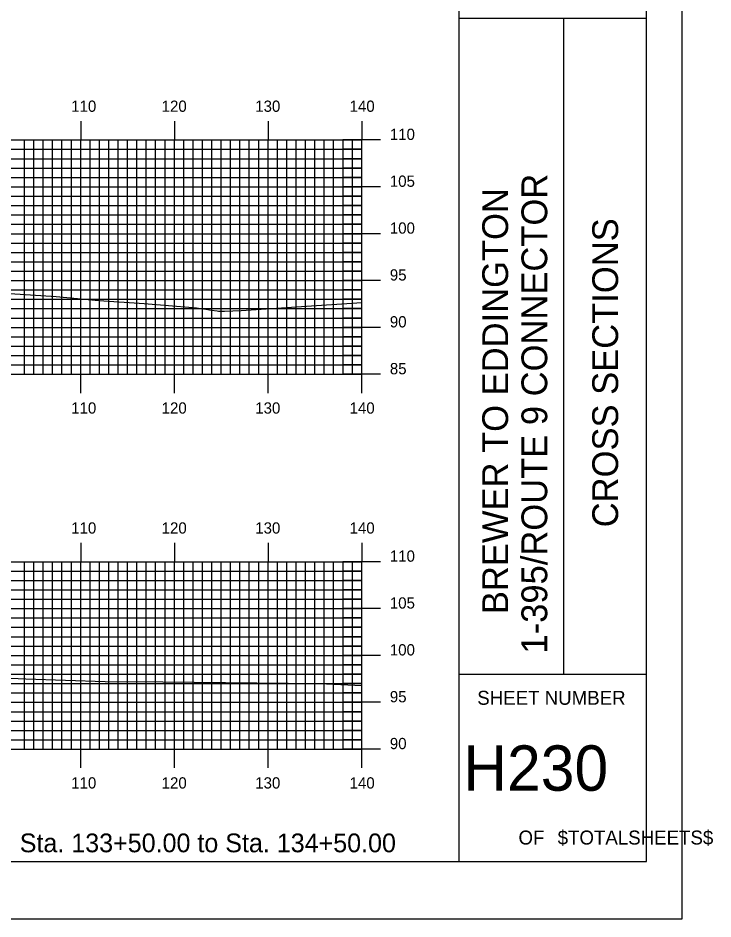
# Model space of a CAD drawing. Extents: x 1774777 to 1775120, y 442591 to 442811.
# Drawn here: x 1775046 to 1775120.2, y 442590.5 to 442686.7 of the extents above; entities that cross this region are included whole.
import ezdxf

# ---------------------------------------------------------------- set-up
doc = ezdxf.new("R2010")
doc.units = 0
for name, color, linetype in [('BORDER', 7, 'Continuous'), ('H_V ANNOTATION', 7, 'Continuous'), ('MAJOR', 7, 'Continuous'), ('MINOR', 7, 'Continuous'), ('PLOT BOUNDARY', 7, 'Continuous'), ('S_Roadway_Centerline', 7, 'Continuous')]:
    doc.layers.add(name, color=color, linetype=linetype)

msp = doc.modelspace()

# ---------------------------------------------------------------- linework, layer by layer
at = {"layer": 'BORDER'}
for p, q in [((1775093.085, 442596.665), (1775093.085, 442806.665)), ((1775093.085, 442686.671), (1775113.085, 442686.671)), ((1775104.267, 442616.671), (1775104.267, 442686.671)), ((1775093.085, 442616.671), (1775113.085, 442616.671))]:
    msp.add_line(p, q, dxfattribs=at)
msp.add_lwpolyline([(1774793.085, 442596.665), (1775113.085, 442596.665), (1775113.085, 442806.665), (1774793.085, 442806.665)], close=True, dxfattribs=at)
at = {"layer": 'MAJOR'}
for p, q in [((1775052.685, 442675.669), (1775052.685, 442673.665)), ((1775062.685, 442675.669), (1775062.685, 442673.665)), ((1775072.685, 442675.669), (1775072.685, 442673.665)), ((1775082.685, 442675.669), (1775082.685, 442673.665)), ((1774802.685, 442673.665), (1775082.685, 442673.665)), ((1774802.685, 442673.665), (1775082.685, 442673.665)), ((1775052.685, 442648.665), (1775052.685, 442673.665)), ((1775062.685, 442648.665), (1775062.685, 442673.665)), ((1775072.685, 442648.665), (1775072.685, 442673.665)), ((1775084.689, 442673.665), (1775080.681, 442673.665)), ((1775082.685, 442648.665), (1775082.685, 442673.665)), ((1775082.685, 442648.665), (1775082.685, 442673.665)), ((1774802.685, 442668.665), (1775082.685, 442668.665)), ((1775084.689, 442668.665), (1775080.681, 442668.665)), ((1774802.685, 442663.665), (1775082.685, 442663.665)), ((1775084.689, 442663.665), (1775080.681, 442663.665)), ((1774802.685, 442658.665), (1775082.685, 442658.665)), ((1775084.689, 442658.665), (1775080.681, 442658.665)), ((1774802.685, 442653.665), (1775082.685, 442653.665)), ((1775084.689, 442653.665), (1775080.681, 442653.665)), ((1774802.685, 442648.665), (1775082.685, 442648.665)), ((1774802.685, 442648.665), (1775082.685, 442648.665)), ((1775052.685, 442646.661), (1775052.685, 442648.665)), ((1775062.685, 442646.661), (1775062.685, 442648.665)), ((1775072.685, 442646.661), (1775072.685, 442648.665)), ((1775084.689, 442648.665), (1775080.681, 442648.665)), ((1775082.685, 442646.661), (1775082.685, 442648.665)), ((1775052.685, 442630.669), (1775052.685, 442628.665)), ((1775062.685, 442630.669), (1775062.685, 442628.665)), ((1775072.685, 442630.669), (1775072.685, 442628.665)), ((1775082.685, 442630.669), (1775082.685, 442628.665)), ((1774802.685, 442628.665), (1775082.685, 442628.665)), ((1774802.685, 442628.665), (1775082.685, 442628.665)), ((1775052.685, 442608.665), (1775052.685, 442628.665)), ((1775062.685, 442608.665), (1775062.685, 442628.665)), ((1775072.685, 442608.665), (1775072.685, 442628.665)), ((1775084.689, 442628.665), (1775080.681, 442628.665)), ((1775082.685, 442608.665), (1775082.685, 442628.665)), ((1775082.685, 442608.665), (1775082.685, 442628.665)), ((1774802.685, 442623.665), (1775082.685, 442623.665)), ((1775084.689, 442623.665), (1775080.681, 442623.665)), ((1774802.685, 442618.665), (1775082.685, 442618.665)), ((1775084.689, 442618.665), (1775080.681, 442618.665)), ((1774802.685, 442613.665), (1775082.685, 442613.665)), ((1775084.689, 442613.665), (1775080.681, 442613.665)), ((1774802.685, 442608.665), (1775082.685, 442608.665)), ((1774802.685, 442608.665), (1775082.685, 442608.665)), ((1775052.685, 442606.661), (1775052.685, 442608.665)), ((1775062.685, 442606.661), (1775062.685, 442608.665)), ((1775072.685, 442606.661), (1775072.685, 442608.665)), ((1775084.689, 442608.665), (1775080.681, 442608.665)), ((1775082.685, 442606.661), (1775082.685, 442608.665))]:
    msp.add_line(p, q, dxfattribs=at)
at = {"layer": 'MINOR'}
for p, q in [((1775046.685, 442648.665), (1775046.685, 442673.665)), ((1775047.685, 442648.665), (1775047.685, 442673.665)), ((1775048.685, 442648.665), (1775048.685, 442673.665)), ((1775049.685, 442648.665), (1775049.685, 442673.665)), ((1775050.685, 442648.665), (1775050.685, 442673.665)), ((1775051.685, 442648.665), (1775051.685, 442673.665)), ((1775053.685, 442648.665), (1775053.685, 442673.665)), ((1775054.685, 442648.665), (1775054.685, 442673.665)), ((1775055.685, 442648.665), (1775055.685, 442673.665)), ((1775056.685, 442648.665), (1775056.685, 442673.665)), ((1775057.685, 442648.665), (1775057.685, 442673.665)), ((1775058.685, 442648.665), (1775058.685, 442673.665)), ((1775059.685, 442648.665), (1775059.685, 442673.665)), ((1775060.685, 442648.665), (1775060.685, 442673.665)), ((1775061.685, 442648.665), (1775061.685, 442673.665)), ((1775063.685, 442648.665), (1775063.685, 442673.665)), ((1775064.685, 442648.665), (1775064.685, 442673.665)), ((1775065.685, 442648.665), (1775065.685, 442673.665)), ((1775066.685, 442648.665), (1775066.685, 442673.665)), ((1775067.685, 442648.665), (1775067.685, 442673.665)), ((1775068.685, 442648.665), (1775068.685, 442673.665)), ((1775069.685, 442648.665), (1775069.685, 442673.665)), ((1775070.685, 442648.665), (1775070.685, 442673.665)), ((1775071.685, 442648.665), (1775071.685, 442673.665)), ((1775073.685, 442648.665), (1775073.685, 442673.665)), ((1775074.685, 442648.665), (1775074.685, 442673.665)), ((1775075.685, 442648.665), (1775075.685, 442673.665)), ((1775076.685, 442648.665), (1775076.685, 442673.665)), ((1775077.685, 442648.665), (1775077.685, 442673.665)), ((1775078.685, 442648.665), (1775078.685, 442673.665)), ((1775079.685, 442648.665), (1775079.685, 442673.665)), ((1775080.685, 442648.665), (1775080.685, 442673.665)), ((1775081.685, 442648.665), (1775081.685, 442673.665)), ((1774802.685, 442672.665), (1775082.685, 442672.665)), ((1775082.685, 442672.665), (1775080.681, 442672.665)), ((1774802.685, 442671.665), (1775082.685, 442671.665)), ((1775082.685, 442671.665), (1775080.681, 442671.665)), ((1774802.685, 442670.665), (1775082.685, 442670.665)), ((1775082.685, 442670.665), (1775080.681, 442670.665)), ((1774802.685, 442669.665), (1775082.685, 442669.665)), ((1775082.685, 442669.665), (1775080.681, 442669.665)), ((1774802.685, 442667.665), (1775082.685, 442667.665)), ((1775082.685, 442667.665), (1775080.681, 442667.665)), ((1774802.685, 442666.665), (1775082.685, 442666.665)), ((1775082.685, 442666.665), (1775080.681, 442666.665)), ((1774802.685, 442665.665), (1775082.685, 442665.665)), ((1775082.685, 442665.665), (1775080.681, 442665.665)), ((1774802.685, 442664.665), (1775082.685, 442664.665)), ((1775082.685, 442664.665), (1775080.681, 442664.665)), ((1774802.685, 442662.665), (1775082.685, 442662.665)), ((1775082.685, 442662.665), (1775080.681, 442662.665)), ((1774802.685, 442661.665), (1775082.685, 442661.665)), ((1775082.685, 442661.665), (1775080.681, 442661.665)), ((1774802.685, 442660.665), (1775082.685, 442660.665)), ((1775082.685, 442660.665), (1775080.681, 442660.665)), ((1774802.685, 442659.665), (1775082.685, 442659.665)), ((1775082.685, 442659.665), (1775080.681, 442659.665)), ((1774802.685, 442657.665), (1775082.685, 442657.665)), ((1775082.685, 442657.665), (1775080.681, 442657.665)), ((1774802.685, 442656.665), (1775082.685, 442656.665)), ((1775082.685, 442656.665), (1775080.681, 442656.665)), ((1774802.685, 442655.665), (1775082.685, 442655.665)), ((1775082.685, 442655.665), (1775080.681, 442655.665)), ((1774802.685, 442654.665), (1775082.685, 442654.665)), ((1775082.685, 442654.665), (1775080.681, 442654.665)), ((1774802.685, 442652.665), (1775082.685, 442652.665)), ((1775082.685, 442652.665), (1775080.681, 442652.665)), ((1774802.685, 442651.665), (1775082.685, 442651.665)), ((1775082.685, 442651.665), (1775080.681, 442651.665)), ((1774802.685, 442650.665), (1775082.685, 442650.665)), ((1775082.685, 442650.665), (1775080.681, 442650.665)), ((1774802.685, 442649.665), (1775082.685, 442649.665)), ((1775082.685, 442649.665), (1775080.681, 442649.665)), ((1775046.685, 442608.665), (1775046.685, 442628.665)), ((1775047.685, 442608.665), (1775047.685, 442628.665)), ((1775048.685, 442608.665), (1775048.685, 442628.665)), ((1775049.685, 442608.665), (1775049.685, 442628.665)), ((1775050.685, 442608.665), (1775050.685, 442628.665)), ((1775051.685, 442608.665), (1775051.685, 442628.665)), ((1775053.685, 442608.665), (1775053.685, 442628.665)), ((1775054.685, 442608.665), (1775054.685, 442628.665)), ((1775055.685, 442608.665), (1775055.685, 442628.665)), ((1775056.685, 442608.665), (1775056.685, 442628.665)), ((1775057.685, 442608.665), (1775057.685, 442628.665)), ((1775058.685, 442608.665), (1775058.685, 442628.665)), ((1775059.685, 442608.665), (1775059.685, 442628.665)), ((1775060.685, 442608.665), (1775060.685, 442628.665)), ((1775061.685, 442608.665), (1775061.685, 442628.665)), ((1775063.685, 442608.665), (1775063.685, 442628.665)), ((1775064.685, 442608.665), (1775064.685, 442628.665)), ((1775065.685, 442608.665), (1775065.685, 442628.665)), ((1775066.685, 442608.665), (1775066.685, 442628.665)), ((1775067.685, 442608.665), (1775067.685, 442628.665)), ((1775068.685, 442608.665), (1775068.685, 442628.665)), ((1775069.685, 442608.665), (1775069.685, 442628.665)), ((1775070.685, 442608.665), (1775070.685, 442628.665)), ((1775071.685, 442608.665), (1775071.685, 442628.665)), ((1775073.685, 442608.665), (1775073.685, 442628.665)), ((1775074.685, 442608.665), (1775074.685, 442628.665)), ((1775075.685, 442608.665), (1775075.685, 442628.665)), ((1775076.685, 442608.665), (1775076.685, 442628.665)), ((1775077.685, 442608.665), (1775077.685, 442628.665)), ((1775078.685, 442608.665), (1775078.685, 442628.665)), ((1775079.685, 442608.665), (1775079.685, 442628.665)), ((1775080.685, 442608.665), (1775080.685, 442628.665)), ((1775081.685, 442608.665), (1775081.685, 442628.665)), ((1774802.685, 442627.665), (1775082.685, 442627.665)), ((1775082.685, 442627.665), (1775080.681, 442627.665)), ((1774802.685, 442626.665), (1775082.685, 442626.665)), ((1775082.685, 442626.665), (1775080.681, 442626.665)), ((1774802.685, 442625.665), (1775082.685, 442625.665)), ((1775082.685, 442625.665), (1775080.681, 442625.665)), ((1774802.685, 442624.665), (1775082.685, 442624.665)), ((1775082.685, 442624.665), (1775080.681, 442624.665)), ((1774802.685, 442622.665), (1775082.685, 442622.665)), ((1775082.685, 442622.665), (1775080.681, 442622.665)), ((1774802.685, 442621.665), (1775082.685, 442621.665)), ((1775082.685, 442621.665), (1775080.681, 442621.665)), ((1774802.685, 442620.665), (1775082.685, 442620.665)), ((1775082.685, 442620.665), (1775080.681, 442620.665)), ((1774802.685, 442619.665), (1775082.685, 442619.665)), ((1775082.685, 442619.665), (1775080.681, 442619.665)), ((1774802.685, 442617.665), (1775082.685, 442617.665)), ((1775082.685, 442617.665), (1775080.681, 442617.665)), ((1774802.685, 442616.665), (1775082.685, 442616.665)), ((1775082.685, 442616.665), (1775080.681, 442616.665)), ((1774802.685, 442615.665), (1775082.685, 442615.665)), ((1775082.685, 442615.665), (1775080.681, 442615.665)), ((1774802.685, 442614.665), (1775082.685, 442614.665)), ((1775082.685, 442614.665), (1775080.681, 442614.665)), ((1774802.685, 442612.665), (1775082.685, 442612.665)), ((1775082.685, 442612.665), (1775080.681, 442612.665)), ((1774802.685, 442611.665), (1775082.685, 442611.665)), ((1775082.685, 442611.665), (1775080.681, 442611.665)), ((1774802.685, 442610.665), (1775082.685, 442610.665)), ((1775082.685, 442610.665), (1775080.681, 442610.665)), ((1774802.685, 442609.665), (1775082.685, 442609.665)), ((1775082.685, 442609.665), (1775080.681, 442609.665))]:
    msp.add_line(p, q, dxfattribs=at)
at = {"layer": 'PLOT BOUNDARY'}
msp.add_lwpolyline([(1774776.898, 442590.547), (1775116.898, 442590.547), (1775116.898, 442810.547), (1774776.898, 442810.547)], close=True, dxfattribs=at)
at = {"layer": 'S_Roadway_Centerline'}
for points in [[(1775039.036, 442657.657), (1775050.067, 442656.974), (1775054.626, 442656.529), (1775059.471, 442656.215), (1775064.651, 442655.802), (1775065.037, 442655.745), (1775065.511, 442655.676), (1775066.056, 442655.598), (1775066.65, 442655.514), (1775067.266, 442655.426), (1775067.401, 442655.407), (1775067.892, 442655.41), (1775067.979, 442655.41), (1775068.023, 442655.41), (1775069.822, 442655.469), (1775082.685, 442656.324)], [(1775000.697, 442618.077), (1775010.952, 442617.962), (1775013.522, 442617.881), (1775026.675, 442617.107), (1775033.775, 442616.742), (1775046.843, 442616.175), (1775055.308, 442615.876), (1775061.468, 442615.86), (1775078.187, 442615.666), (1775082.685, 442615.47)]]:
    msp.add_lwpolyline(points, dxfattribs=at)

# ---------------------------------------------------------------- texts
at = {"layer": 'BORDER'}
for s, p in [('1-395/ROUTE 9 CONNECTOR', (1775102.488, 442618.865)), ('BREWER TO EDDINGTON', (1775098.308, 442623.074)), ('CROSS SECTIONS', (1775110.054, 442632.339))]:
    msp.add_text(s, height=2.75575, rotation=90, dxfattribs=at).set_placement(p)
for s, height, p in [('SHEET NUMBER', 1.49054, (1775095.016, 442613.398)), ('H230', 4.8388, (1775093.525, 442604.23)), ('OF', 1.4905, (1775099.419, 442598.491)), ('$TOTALSHEETS$', 1.49054, (1775103.598, 442598.491))]:
    msp.add_text(s, height=height, dxfattribs=at).set_placement(p)
at = {"layer": 'H_V ANNOTATION'}
for s, height, p in [('110', 1.2, (1775051.668, 442676.665)), ('120', 1.2, (1775061.326, 442676.665)), ('130', 1.2, (1775071.315, 442676.665)), ('140', 1.2, (1775081.39, 442676.665)), ('110', 1.2, (1775085.685, 442673.665)), ('105', 1.2, (1775085.685, 442668.665)), ('100', 1.2, (1775085.685, 442663.665)), ('95', 1.2, (1775085.685, 442658.665)), ('90', 1.2, (1775085.685, 442653.665)), ('85', 1.2, (1775085.685, 442648.665)), ('110', 1.2, (1775051.668, 442644.465)), ('120', 1.2, (1775061.326, 442644.465)), ('130', 1.2, (1775071.315, 442644.465)), ('140', 1.2, (1775081.39, 442644.465)), ('110', 1.2, (1775051.668, 442631.665)), ('120', 1.2, (1775061.326, 442631.665)), ('130', 1.2, (1775071.315, 442631.665)), ('140', 1.2, (1775081.39, 442631.665)), ('110', 1.2, (1775085.685, 442628.665)), ('105', 1.2, (1775085.685, 442623.665)), ('100', 1.2, (1775085.685, 442618.665)), ('95', 1.2, (1775085.685, 442613.665)), ('90', 1.2, (1775085.685, 442608.665)), ('110', 1.2, (1775051.668, 442604.465)), ('120', 1.2, (1775061.326, 442604.465)), ('130', 1.2, (1775071.315, 442604.465)), ('140', 1.2, (1775081.39, 442604.465)), ('Sta. 133+50.00 to Sta. 134+50.00', 2.0004, (1775046.177, 442597.665))]:
    msp.add_text(s, height=height, dxfattribs=at).set_placement(p)

doc.saveas('drawing.dxf')
